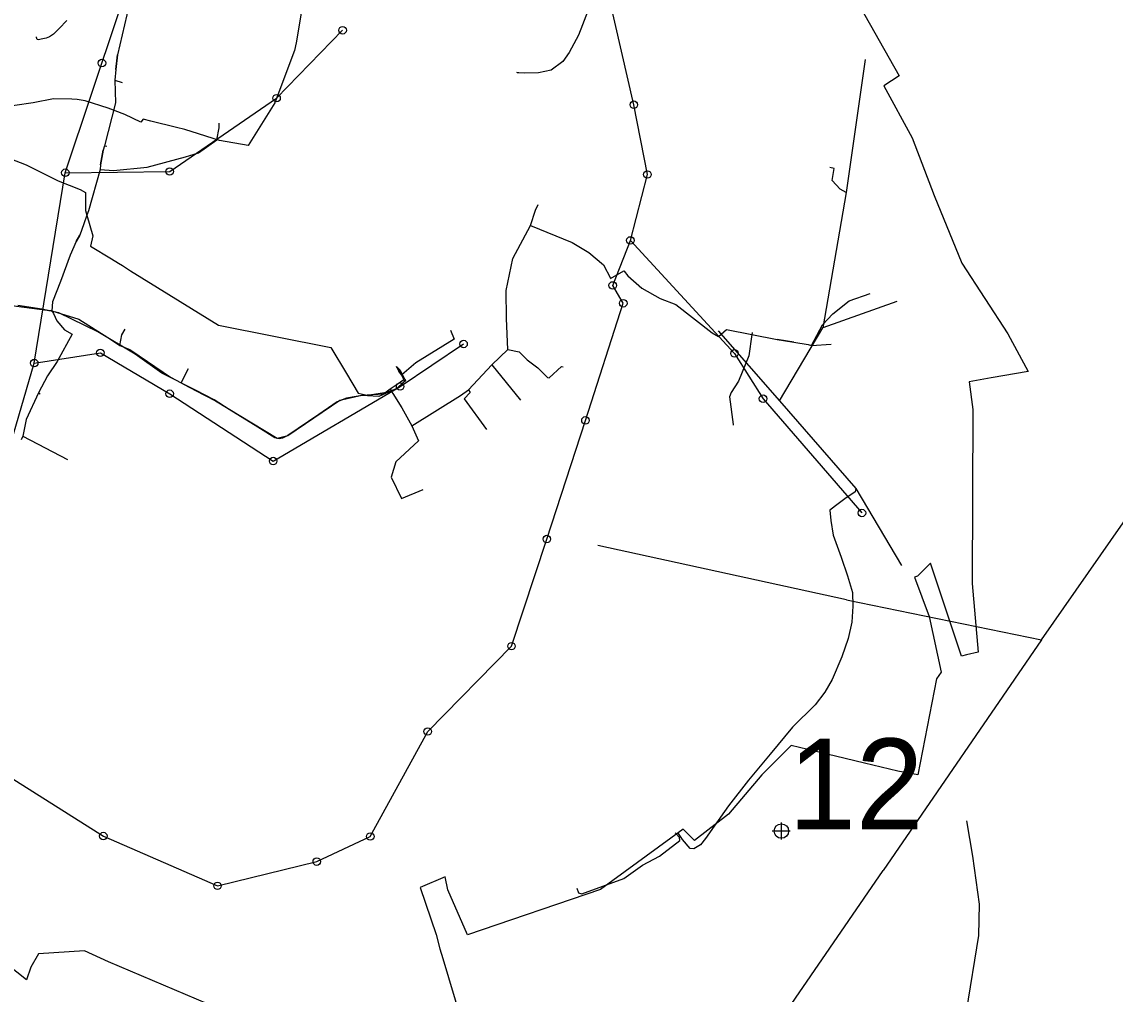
# Model space of a CAD drawing. Extents: x -543464 to -538545, y -1098769 to -1093672.
# Drawn here: x -541288.9 to -540987.8, y -1097101.5 to -1096833.9 of the extents above; entities that cross this region are included whole.
import ezdxf

# ---------------------------------------------------------------- set-up
doc = ezdxf.new("R2010")
doc.units = 0
for name, color, linetype in [('00_IGP_sondy', 7, 'Continuous'), ('01_OBVOD PÚ', 7, 'Continuous'), ('03_PC_NAVRH', 7, 'Continuous'), ('07_ELEKTRO', 7, 'Continuous'), ('07_KANALIZACE', 7, 'Continuous'), ('07_SDĚLOVACÍ', 7, 'Continuous'), ('07_VODOVOD', 7, 'Continuous')]:
    doc.layers.add(name, color=color, linetype=linetype)

msp = doc.modelspace()

# ---------------------------------------------------------------- linework, layer by layer
at = {"layer": '00_IGP_sondy'}
for p, q in [((-541079.74, -1097059.02), (-541079.74, -1097054.3)), ((-541077.3, -1097056.66), (-541082.27, -1097056.66)), ((-541079.74, -1097056.66), (-541079.74, -1097056.66))]:
    msp.add_line(p, q, dxfattribs=at)
msp.add_circle((-541079.74, -1097056.66), 2, dxfattribs=at)
at = {"layer": '01_OBVOD PÚ'}
for p, q in [((-541063.85, -1096819.54), (-541047.31, -1096848.82)), ((-541047.31, -1096848.82), (-541051.54, -1096851.52)), ((-541051.54, -1096851.52), (-541043.69, -1096865.85)), ((-541043.69, -1096865.85), (-541037.68, -1096881.72)), ((-541037.68, -1096881.72), (-541030.07, -1096900.37)), ((-541030.07, -1096900.37), (-541017.39, -1096919.81)), ((-541017.39, -1096919.81), (-541011.83, -1096930.12)), ((-541011.83, -1096930.12), (-541021.98, -1096931.9)), ((-541021.98, -1096931.9), (-541028.01, -1096932.97)), ((-541028.01, -1096932.97), (-541027, -1096940.58)), ((-541027, -1096940.58), (-541027.21, -1096988.49)), ((-541038.72, -1096982.93), (-541042.27, -1096986.46)), ((-541030.17, -1097008.54), (-541038.72, -1096982.93)), ((-541042.27, -1096986.46), (-541043.09, -1096986.82)), ((-541043.09, -1096986.82), (-541039.01, -1096997.56)), ((-541027.21, -1096988.49), (-541025.52, -1097007.4)), ((-541039.01, -1096997.56), (-541035.75, -1097012.89)), ((-541028.79, -1097008.15), (-541030.17, -1097008.54)), ((-541025.52, -1097007.4), (-541028.79, -1097008.15)), ((-541035.75, -1097012.89), (-541036.99, -1097014.79)), ((-541077.03, -1097033.1), (-541085.13, -1097041.14)), ((-541047.67, -1097040.18), (-541056.81, -1097037.95)), ((-541085.13, -1097041.14), (-541094.31, -1097051.98)), ((-541094.31, -1097051.98), (-541103.65, -1097059.24)), ((-541287.59, -1097097.64), (-541340.71, -1097055.21)), ((-541106.8, -1097056.17), (-541129.55, -1097072.75)), ((-541103.65, -1097059.24), (-541106.8, -1097056.17)), ((-541172.35, -1097069.25), (-541179.22, -1097072.16)), ((-541171.57, -1097072.88), (-541172.35, -1097069.25)), ((-541179.22, -1097072.16), (-541174.8, -1097085.16)), ((-541166.16, -1097085.21), (-541171.57, -1097072.88)), ((-541129.55, -1097072.75), (-541166.16, -1097085.21)), ((-541174.8, -1097085.16), (-541173.77, -1097089.04)), ((-541284.25, -1097090.45), (-541286.36, -1097094.08)), ((-541271.63, -1097089.65), (-541284.25, -1097090.45)), ((-541265.03, -1097092.62), (-541271.63, -1097089.65)), ((-541173.77, -1097089.04), (-541172.95, -1097091.71)), ((-541228.7, -1097108.08), (-541265.03, -1097092.62)), ((-541172.95, -1097091.71), (-541167.82, -1097108.77)), ((-541286.36, -1097094.08), (-541287.59, -1097097.64))]:
    msp.add_line(p, q, dxfattribs=at)
for points in [[(-541036.99, -1097014.79), (-541042.14, -1097041.18), (-541047.67, -1097040.18)], [(-541056.81, -1097037.95), (-541072.47, -1097034.18), (-541077.03, -1097033.1)]]:
    msp.add_lwpolyline(points, dxfattribs=at)
at = {"layer": '03_PC_NAVRH'}
msp.add_lwpolyline([(-540979.54, -1097167.49), (-540989.93, -1097161.77), (-540998.77, -1097156.56), (-541004.22, -1097153.49), (-541011.29, -1097149), (-541017.98, -1097143.85), (-541022.21, -1097140.11), (-541024.65, -1097136.85), (-541027.31, -1097131.91), (-541028.83, -1097127.13), (-541029.75, -1097119.43), (-541029.95, -1097113.57), (-541028.78, -1097106.32), (-541025.38, -1097085.36), (-541025.19, -1097076.76), (-541027.04, -1097063.6), (-541028.65, -1097053.87)], dxfattribs=at)
at = {"layer": '07_ELEKTRO'}
for points in [[(-541056.71, -1096844.3), (-541061.88, -1096880.94)], [(-541061.88, -1096880.94), (-541063.53, -1096879.95), (-541065.72, -1096877.57), (-541065.24, -1096874.26), (-541066.41, -1096874.03)], [(-541061.88, -1096880.94), (-541068.3, -1096918.16)], [(-541047.99, -1096910.86), (-541068.3, -1096918.16)], [(-541097.11, -1096918.97), (-541080.22, -1096938.27)], [(-541080.22, -1096938.27), (-541068.3, -1096918.16)], [(-541080.22, -1096938.27), (-541059.22, -1096962.36)], [(-541008.16, -1097003.99), (-540972.72, -1096953.26)], [(-541059.22, -1096962.36), (-541059.45, -1096963.26), (-541062.24, -1096965.22), (-541064.1, -1096966.58), (-541066.37, -1096968.29), (-541066.15, -1096971.16), (-541065.46, -1096975.23), (-541063.24, -1096981.3), (-541061.54, -1096986.4), (-541060.2, -1096990.98), (-541060.08, -1096994.74), (-541060.31, -1096999.14), (-541061.31, -1097003.65), (-541063.1, -1097008.72), (-541065.76, -1097014.96), (-541067.82, -1097018.46), (-541070.44, -1097021.92), (-541076.68, -1097028.07), (-541082.79, -1097035.49), (-541088.81, -1097042.65), (-541094.3, -1097049.68), (-541098.28, -1097055.32), (-541100.59, -1097058.69), (-541102.03, -1097060.43), (-541103.81, -1097061.59), (-541104.88, -1097061.48), (-541106.95, -1097058.98), (-541108.03, -1097057.37), (-541108.75, -1097057.39)], [(-541059.22, -1096962.36), (-541046.66, -1096983.55)], [(-541061.79, -1096993.04), (-541130.29, -1096978.06)], [(-541061.79, -1096993.04), (-541008.16, -1097003.99)], [(-541008.16, -1097003.99), (-541051.69, -1097067.5)], [(-541136.1, -1097072.38), (-541135.57, -1097073.64), (-541134.67, -1097073.94), (-541123.08, -1097069.76), (-541117.96, -1097066.04), (-541113.34, -1097063.59), (-541107.74, -1097059.24), (-541107.75, -1097058.39), (-541108.75, -1097057.39)], [(-541108.75, -1097057.39), (-541108.99, -1097057.2)], [(-541081.11, -1097110.23), (-541051.69, -1097067.5)]]:
    msp.add_lwpolyline(points, dxfattribs=at)
at = {"layer": '07_KANALIZACE'}
for p, q in [((-541120.37, -1096856.73), (-541129.41, -1096817.43)), ((-541218.73, -1096854.94), (-541200.55, -1096836.25)), ((-541248.16, -1096875.11), (-541218.73, -1096854.94)), ((-541276.89, -1096875.45), (-541248.16, -1096875.11)), ((-541126.18, -1096906.47), (-541121.31, -1096894.09)), ((-541121.31, -1096894.09), (-541092.65, -1096925.18)), ((-541123.27, -1096911.39), (-541126.18, -1096906.47)), ((-541133.69, -1096943.62), (-541123.27, -1096911.39)), ((-541285.45, -1096927.85), (-541267.25, -1096925.02)), ((-541267.25, -1096925.02), (-541248.16, -1096936.28)), ((-541184.72, -1096934.3), (-541167.24, -1096922.59)), ((-541092.65, -1096925.18), (-541084.79, -1096937.65)), ((-541248.16, -1096936.28), (-541219.66, -1096954.81)), ((-541219.66, -1096954.81), (-541184.72, -1096934.3)), ((-541084.79, -1096937.65), (-541057.55, -1096969.11)), ((-541144.32, -1096976.28), (-541133.69, -1096943.62)), ((-541154.04, -1097005.76), (-541144.32, -1096976.28)), ((-541177.11, -1097029.25), (-541154.04, -1097005.76)), ((-541192.93, -1097058.16), (-541177.11, -1097029.25)), ((-541306.21, -1097032.93), (-541266.42, -1097058.03)), ((-541266.42, -1097058.03), (-541235, -1097071.74)), ((-541207.66, -1097065.07), (-541192.93, -1097058.16)), ((-541235, -1097071.74), (-541207.66, -1097065.07))]:
    msp.add_line(p, q, dxfattribs=at)
for points in [[(-541276.89, -1096875.45), (-541262.26, -1096831.61), (-541228.38, -1096829.44), (-541211.94, -1096780.77), (-541201.22, -1096747.47), (-541185.03, -1096696.99), (-541212.27, -1096688), (-541227.4, -1096683.38), (-541251.25, -1096676.2), (-541285.18, -1096665.6)], [(-541121.31, -1096894.09), (-541116.64, -1096875.94), (-541120.37, -1096856.73)], [(-541315.35, -1097000.38), (-541296.08, -1096964.08), (-541285.45, -1096927.85), (-541276.89, -1096875.45)]]:
    msp.add_lwpolyline(points, dxfattribs=at)
for centre in [(-541200.55, -1096836.25), (-541266.81, -1096845.26), (-541218.73, -1096854.94), (-541120.37, -1096856.73), (-541276.89, -1096875.45), (-541248.16, -1096875.11), (-541116.64, -1096875.94), (-541121.31, -1096894.09), (-541126.18, -1096906.47), (-541123.27, -1096911.39), (-541167.24, -1096922.59), (-541267.25, -1096925.02), (-541092.65, -1096925.18), (-541285.45, -1096927.85), (-541184.72, -1096934.3), (-541248.16, -1096936.28), (-541084.79, -1096937.65), (-541133.69, -1096943.62), (-541219.66, -1096954.81), (-541057.55, -1096969.11), (-541144.32, -1096976.28), (-541154.04, -1097005.76), (-541177.11, -1097029.25), (-541266.42, -1097058.03), (-541192.93, -1097058.16), (-541207.66, -1097065.07), (-541235, -1097071.74)]:
    msp.add_circle(centre, 1.03, dxfattribs=at)
at = {"layer": '07_SDĚLOVACÍ'}
for points in [[(-541250.7, -1096806.39), (-541251.87, -1096813.23), (-541256, -1096822.37), (-541256.86, -1096823), (-541259.29, -1096829.26), (-541262.54, -1096842.99), (-541262.95, -1096847.08), (-541263.22, -1096849.99)], [(-541262.95, -1096847.08), (-541262.54, -1096842.99)], [(-541263.22, -1096849.99), (-541263.04, -1096856.26), (-541266.12, -1096868.01)], [(-541263.22, -1096849.99), (-541261.27, -1096850.64)], [(-541267.29, -1096874.6), (-541263.64, -1096874.87), (-541254.37, -1096873.95), (-541243.83, -1096871.12), (-541240.26, -1096869.99), (-541235.19, -1096866.36), (-541234.51, -1096863.14), (-541234.54, -1096861.79)], [(-541319.32, -1096863.02), (-541318.62, -1096863.23), (-541292.19, -1096871.52), (-541287.65, -1096873.31), (-541278.85, -1096877.68), (-541272.84, -1096880.06), (-541271.33, -1096880.85), (-541271.32, -1096885.82), (-541270.94, -1096887.14)], [(-541235.19, -1096866.36), (-541234.51, -1096863.14)], [(-541266.12, -1096868.01), (-541266.45, -1096869.28), (-541267.21, -1096873.26), (-541267.29, -1096874.6)], [(-541267.21, -1096873.26), (-541266.45, -1096869.28)], [(-541266.12, -1096868.01), (-541265.5, -1096868.18)], [(-541267.29, -1096874.6), (-541270.51, -1096885.94), (-541270.94, -1096887.14)], [(-541278.85, -1096877.68), (-541272.84, -1096880.06)], [(-541148.79, -1096889.96), (-541147.41, -1096885.78), (-541146.72, -1096884.21)], [(-541148.79, -1096889.96), (-541147.41, -1096885.78)], [(-541270.94, -1096887.14), (-541271.79, -1096889.48)], [(-541270.94, -1096887.14), (-541269.34, -1096892.78), (-541269.96, -1096895.63), (-541264.19, -1096899.14), (-541262.22, -1096900.35), (-541261.14, -1096900.98), (-541258.91, -1096902.48), (-541234.68, -1096917.44), (-541203.79, -1096923.6), (-541199.43, -1096930.74)], [(-541280.6, -1096913.49), (-541281.4, -1096913.47), (-541281.88, -1096913.42), (-541290.35, -1096912.23), (-541294.21, -1096911.61), (-541298.79, -1096909.69), (-541299.48, -1096909.62), (-541304, -1096912.11), (-541324.02, -1096903.38), (-541353.28, -1096889.87), (-541356.18, -1096889.86), (-541357.84, -1096889.74)], [(-541271.79, -1096889.48), (-541272.94, -1096892.63), (-541273.89, -1096894.37), (-541275.57, -1096898.14), (-541278.18, -1096905.35), (-541280.45, -1096911), (-541280.6, -1096913.49)], [(-541155.01, -1096924.1), (-541155.46, -1096915.54), (-541155.5, -1096907.9), (-541153.67, -1096899.1), (-541148.79, -1096889.96)], [(-541148.79, -1096889.96), (-541137.35, -1096894.62), (-541132.75, -1096897.39), (-541128.73, -1096900.84), (-541126.81, -1096904.49)], [(-541273.89, -1096894.37), (-541272.94, -1096892.63)], [(-541264.19, -1096899.14), (-541262.22, -1096900.35)], [(-541126.81, -1096904.49), (-541126.77, -1096904.56), (-541123.11, -1096902.5), (-541123.04, -1096902.58)], [(-541126.77, -1096904.56), (-541123.11, -1096902.5)], [(-541123.04, -1096902.58), (-541122, -1096903.81), (-541118.2, -1096907.27), (-541113.13, -1096910.03), (-541108.77, -1096911.69), (-541098.8, -1096919.55), (-541097.05, -1096920.56), (-541094.87, -1096918.56), (-541087.86, -1096919.96)], [(-541071.47, -1096923.05), (-541068.42, -1096917.28), (-541065.61, -1096914.29), (-541061.08, -1096910.72), (-541055.31, -1096908.72)], [(-541281.88, -1096913.42), (-541290.35, -1096912.23)], [(-541185.75, -1096928.79), (-541184.69, -1096929.76), (-541183.38, -1096932.48), (-541183.65, -1096932.98), (-541185.66, -1096934.83), (-541190.57, -1096937.02), (-541195.25, -1096936.73), (-541199.48, -1096937.46), (-541202, -1096938.55), (-541207.05, -1096942.01), (-541215.59, -1096947.76), (-541217.05, -1096948.47), (-541218, -1096948.72), (-541219.19, -1096948.41), (-541223.88, -1096945.52), (-541231.74, -1096940.65), (-541235.89, -1096937.93), (-541241.01, -1096935.29), (-541250.28, -1096930.6), (-541257.66, -1096925.35), (-541267.94, -1096919.25), (-541278.71, -1096914), (-541283.38, -1096913.03), (-541289.98, -1096912.03)], [(-541108.77, -1096911.69), (-541098.8, -1096919.55)], [(-541280.6, -1096913.49), (-541280.13, -1096914.2), (-541279.26, -1096916.24), (-541277.09, -1096918.68), (-541274.97, -1096919.93), (-541279.15, -1096927.4), (-541281.83, -1096931.34), (-541284.25, -1096936.01)], [(-541280.6, -1096913.49), (-541273.16, -1096915.73), (-541265.14, -1096920.8), (-541261.84, -1096923.03)], [(-541261.84, -1096923.03), (-541261.36, -1096920.08), (-541260.45, -1096918.51)], [(-541170.86, -1096918.83), (-541169.81, -1096921.22), (-541180.42, -1096927.77), (-541184.26, -1096931.06)], [(-541274.97, -1096919.93), (-541279.15, -1096927.4)], [(-541087.86, -1096919.96), (-541088.71, -1096925.89), (-541091.51, -1096932.84), (-541093.59, -1096935.97), (-541094.02, -1096937.17), (-541093.02, -1096944.72), (-541093, -1096944.95)], [(-541087.86, -1096919.96), (-541087.69, -1096919.63), (-541087.72, -1096919.44)], [(-541087.86, -1096919.96), (-541080.87, -1096921.38), (-541076.32, -1096922.05), (-541072.38, -1096922.72), (-541071.47, -1096923.05)], [(-541076.32, -1096922.05), (-541080.87, -1096921.38)], [(-541261.84, -1096923.03), (-541259.16, -1096924.07), (-541258.57, -1096924.47)], [(-541258.57, -1096924.47), (-541247.97, -1096931.68), (-541244.95, -1096933.29)], [(-541203.79, -1096923.6), (-541199.43, -1096930.74), (-541196.29, -1096936.16), (-541193.74, -1096936.68), (-541188.4, -1096935.86), (-541185.66, -1096934.83), (-541183.17, -1096932.68), (-541184.26, -1096931.06), (-541184.78, -1096930.27)], [(-541159.42, -1096928.31), (-541155.01, -1096924.1)], [(-541155.01, -1096924.1), (-541151.95, -1096924.73), (-541149.71, -1096926.93), (-541146.81, -1096929.15), (-541144.13, -1096931.86), (-541143.65, -1096931.88), (-541140.26, -1096928.78), (-541139.83, -1096928.84)], [(-541155.01, -1096924.1), (-541151.95, -1096924.73), (-541149.71, -1096926.93), (-541146.81, -1096929.15), (-541144.13, -1096931.86), (-541143.65, -1096931.88), (-541140.26, -1096928.78), (-541139.83, -1096928.84)], [(-541076.32, -1096922.05), (-541072.38, -1096922.72)], [(-541071.47, -1096923.05), (-541066.03, -1096922.62)], [(-541088.71, -1096925.89), (-541091.51, -1096932.84)], [(-541244.95, -1096933.29), (-541243.01, -1096929.35)], [(-541199.43, -1096930.74), (-541196.29, -1096936.16), (-541193.74, -1096936.68), (-541188.4, -1096935.86), (-541185.66, -1096934.83), (-541183.17, -1096932.68), (-541184.26, -1096931.06)], [(-541187.44, -1096934.96), (-541185.81, -1096933.87), (-541183.65, -1096932.39), (-541184.32, -1096931.12), (-541185.08, -1096930.06), (-541185.75, -1096928.79)], [(-541184.26, -1096931.06), (-541184.78, -1096930.27), (-541185.75, -1096928.79)], [(-541165.85, -1096935.22), (-541159.42, -1096928.31)], [(-541159.42, -1096928.31), (-541151.6, -1096938.05)], [(-541244.95, -1096933.29), (-541244.37, -1096933.61)], [(-541244.95, -1096933.29), (-541244.37, -1096933.61)], [(-541244.37, -1096933.61), (-541242.46, -1096934.66)], [(-541284.25, -1096936.01), (-541287.69, -1096943.35), (-541288.63, -1096947.99)], [(-541284.25, -1096936.01), (-541283.85, -1096936.27)], [(-541242.46, -1096934.66), (-541241.03, -1096935.44)], [(-541241.03, -1096935.44), (-541235.51, -1096938.26), (-541218.56, -1096948.54), (-541215.59, -1096947.76), (-541201.27, -1096938.07), (-541195.29, -1096936.68), (-541189.33, -1096936.31), (-541187.44, -1096934.96)], [(-541187.44, -1096934.96), (-541186.74, -1096936.22), (-541184.22, -1096940.12), (-541181.52, -1096945.15)], [(-541186.74, -1096936.22), (-541184.22, -1096940.12)], [(-541181.52, -1096945.15), (-541168.13, -1096936.75), (-541165.85, -1096935.22)], [(-541165.85, -1096935.22), (-541165.42, -1096935.98), (-541167.1, -1096937.69), (-541160.93, -1096946.13)], [(-541215.59, -1096947.76), (-541201.27, -1096938.07)], [(-541181.52, -1096945.15), (-541179.63, -1096949.29), (-541185.86, -1096955), (-541187.19, -1096959.25), (-541184.35, -1096965.11), (-541178.35, -1096962.65)], [(-541288.63, -1096947.99), (-541289.08, -1096948.94)], [(-541288.63, -1096947.99), (-541276.33, -1096954.35)]]:
    msp.add_lwpolyline(points, dxfattribs=at)
at = {"layer": '07_VODOVOD'}
for p, q in [((-541152.37, -1096847.94), (-541152.56, -1096847.9)), ((-541151.99, -1096848), (-541152.37, -1096847.94))]:
    msp.add_line(p, q, dxfattribs=at)
for points in [[(-541209.93, -1096819.13), (-541209.94, -1096819.32), (-541213.29, -1096839.7), (-541213.79, -1096841.83), (-541219.19, -1096856.2), (-541226.59, -1096867.94), (-541234.42, -1096866.56), (-541243.95, -1096863.55)], [(-541128.46, -1096816.96), (-541129.92, -1096819.59), (-541131.37, -1096824.23), (-541132.96, -1096830.7), (-541135.59, -1096837.59), (-541138.19, -1096842.34), (-541139.87, -1096844.83), (-541143.15, -1096847.19), (-541146.64, -1096847.96), (-541150.48, -1096848.03), (-541151.99, -1096848)], [(-541276.46, -1096833.53), (-541278.57, -1096835.73), (-541280.17, -1096837.28), (-541281.21, -1096838.08), (-541282.12, -1096838.38), (-541283.55, -1096838.72), (-541284.23, -1096838.88), (-541284.62, -1096838.76), (-541284.85, -1096838.2), (-541284.82, -1096838.02)], [(-541255.47, -1096860.67), (-541256.06, -1096861.52), (-541260.5, -1096859.46), (-541265.1, -1096857.66), (-541271.47, -1096855.69), (-541273.67, -1096855.33), (-541275.13, -1096855.23), (-541280.16, -1096855.15), (-541285.7, -1096856.25), (-541295.93, -1096857.64), (-541301.58, -1096861.78), (-541307.54, -1096866.12), (-541326.02, -1096878.94), (-541340.28, -1096889.08), (-541342.74, -1096887.72), (-541349.22, -1096892.59), (-541353.25, -1096895.09)], [(-541243.95, -1096863.55), (-541246.27, -1096862.99), (-541253.36, -1096861.27), (-541255.47, -1096860.67)]]:
    msp.add_lwpolyline(points, dxfattribs=at)

# ---------------------------------------------------------------- texts
at = {"layer": '00_IGP_sondy'}
msp.add_text('12', height=25, dxfattribs=at).set_placement((-541077.79, -1097056.2))

doc.saveas('drawing.dxf')
